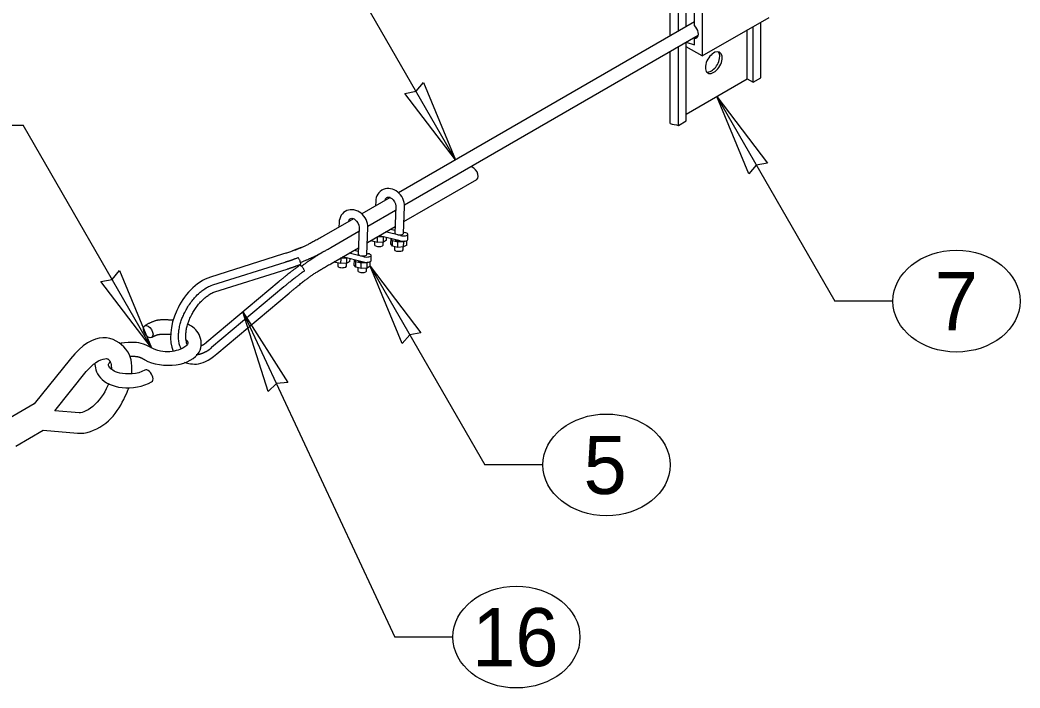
# Model space of a CAD drawing. Extents: x 99862 to 104211, y 98939 to 102076.
# Drawn here: x 101538.3 to 101813.6, y 101580.1 to 101763.9 of the extents above; entities that cross this region are included whole.
import ezdxf

# ---------------------------------------------------------------- set-up
doc = ezdxf.new("R2010")
doc.units = 0
for name, color, linetype in [('Default', 7, 'Continuous'), ('Level 15', 7, 'Continuous'), ('Level 2', 7, 'Continuous'), ('Level 20', 7, 'Continuous'), ('Level 3', 7, 'Continuous'), ('Level 4', 7, 'Continuous'), ('Level 6', 7, 'Continuous')]:
    doc.layers.add(name, color=color, linetype=linetype)

msp = doc.modelspace()

# ---------------------------------------------------------------- linework, layer by layer
at = {"layer": 'Default'}
for p, q in [((101717.25, 101759.56), (101717.25, 101858.02)), ((101719.53, 101760.88), (101719.53, 101857.5)), ((101721.65, 101762.1), (101721.65, 101857.19)), ((101726.09, 101782.05), (101726.09, 101754.01)), ((101723.96, 101762.39), (101723.96, 101781.42)), ((101726.09, 101754.01), (101744.49, 101764.64)), ((101742.18, 101747.99), (101742.18, 101763.3)), ((101738.47, 101747.69), (101738.47, 101761.16)), ((101740.06, 101746.77), (101740.06, 101762.08)), ((101721.65, 101736.14), (101721.65, 101757.77)), ((101721.68, 101757.79), (101723.96, 101757.09)), ((101723.96, 101758.93), (101724.93, 101759.49)), ((101723.96, 101757.09), (101723.96, 101758.93)), ((101717.25, 101735.44), (101717.25, 101755.23)), ((101719.53, 101734.92), (101719.53, 101756.55)), ((101726.09, 101754.01), (101721.65, 101756.57)), ((101721.65, 101737.98), (101738.47, 101747.69)), ((101738.47, 101747.69), (101740.06, 101746.77)), ((101740.06, 101746.77), (101742.18, 101747.99)), ((101719.53, 101734.92), (101721.65, 101736.14))]:
    msp.add_line(p, q, dxfattribs=at)
for centre, major_axis, start_param, end_param in [((101723.43, 101760.97), (1.13, -1.95), 0, 2.016358), ((101723.43, 101760.97), (1.13, -1.95), 5.837624, 6.283185), ((101729.26, 101752.18), (-1.64, -2.84), 2.543744, 6.283185), ((101728.6, 101752.56), (1.64, 2.84), 3.926991, 6.079755), ((101729.26, 101752.18), (-1.64, -2.84), 6.283185, 8.826929), ((101728.6, 101752.56), (1.64, 2.84), 3.345023, 3.926991), ((101725.02, 101744.82), (-18.02, 0), 1.125235, 1.261517)]:
    msp.add_ellipse(centre, major_axis=major_axis, ratio=0.57735, start_param=start_param, end_param=end_param, dxfattribs=at)
at = {"layer": 'Level 15'}
for p, q in [((101658.16, 101725.45), (101625.66, 101781.74)), ((101730.06, 101742.83), (101762.56, 101686.54)), ((101523.11, 101734.94), (101539.11, 101734.94)), ((101574.48, 101673.67), (101539.11, 101734.94)), ((101634.65, 101696.12), (101666.21, 101641.47)), ((101778.56, 101686.54), (101762.56, 101686.54)), ((101599.64, 101683.62), (101641.42, 101594.08)), ((101682.21, 101641.47), (101666.21, 101641.47)), ((101657.42, 101594.08), (101641.42, 101594.08))]:
    msp.add_line(p, q, dxfattribs=at)
for points in [[(101658.16, 101725.45), (101644.16, 101743.72), (101647.28, 101744.3), (101649.33, 101746.71)], [(101730.06, 101742.83), (101744.06, 101724.55), (101740.95, 101723.98), (101738.89, 101721.57)], [(101574.48, 101673.67), (101560.49, 101691.95), (101563.6, 101692.52), (101565.65, 101694.93)], [(101634.65, 101696.12), (101648.65, 101677.85), (101645.54, 101677.27), (101643.48, 101674.86)], [(101599.64, 101683.62), (101612, 101664.19), (101608.85, 101663.89), (101606.59, 101661.67)]]:
    msp.add_lwpolyline(points, close=True, dxfattribs=at)
at = {"layer": 'Level 2'}
for p, q in [((101636.19, 101714.01), (101636.15, 101712.74)), ((101641.69, 101712.68), (101641.46, 101705.25)), ((101643.86, 101705.18), (101644.1, 101712.61)), ((101626.11, 101708.19), (101626.07, 101706.92)), ((101631.61, 101706.86), (101631.38, 101699.43)), ((101633.78, 101699.36), (101634.02, 101706.79)), ((101642.95, 101703.12), (101637.11, 101704.52)), ((101643, 101704.59), (101638.92, 101705.57)), ((101640.29, 101706.35), (101641.48, 101706.07)), ((101643.87, 101705.49), (101644.21, 101705.41)), ((101644.99, 101703.47), (101645.04, 101704.94)), ((101635.22, 101703.03), (101635.02, 101703.32)), ((101635.22, 101703.03), (101635.24, 101703.44)), ((101636.67, 101702.68), (101635.22, 101703.03)), ((101635.84, 101702.88), (101635.82, 101702.04)), ((101636.72, 101704.13), (101636.51, 101704.18)), ((101636.67, 101702.68), (101636.72, 101704.13)), ((101638.31, 101702.78), (101636.67, 101702.68)), ((101638.32, 101704.23), (101636.72, 101704.13)), ((101638.22, 101701.96), (101638.25, 101702.78)), ((101638.31, 101702.78), (101638.35, 101704.22)), ((101639.17, 101703.28), (101638.31, 101702.78)), ((101639.17, 101703.28), (101639.19, 101704.02)), ((101640.37, 101702.29), (101640.42, 101703.73)), ((101640.79, 101701.69), (101640.37, 101702.29)), ((101640.83, 101703.14), (101640.43, 101703.72)), ((101640.79, 101701.69), (101640.83, 101703.14)), ((101642.28, 101702.79), (101640.83, 101703.14)), ((101642.24, 101701.34), (101642.28, 101702.79)), ((101643.92, 101702.89), (101642.28, 101702.79)), ((101643.87, 101701.45), (101643.92, 101702.89)), ((101644.73, 101701.94), (101643.87, 101701.45)), ((101644.2, 101703.06), (101643.92, 101702.89)), ((101644.73, 101701.94), (101644.77, 101703.22)), ((101632.92, 101698.77), (101628.84, 101699.75)), ((101630.21, 101700.53), (101631.4, 101700.25)), ((101633.79, 101699.67), (101634.13, 101699.59)), ((101634.91, 101697.65), (101634.95, 101699.12)), ((101642.24, 101701.34), (101640.79, 101701.69)), ((101641.34, 101701.56), (101641.32, 101700.72)), ((101643.87, 101701.45), (101642.24, 101701.34)), ((101643.72, 101700.64), (101643.75, 101701.44)), ((101625.14, 101697.21), (101624.94, 101697.5)), ((101625.14, 101697.21), (101625.16, 101697.62)), ((101626.59, 101696.86), (101625.14, 101697.21)), ((101625.76, 101697.06), (101625.74, 101696.22)), ((101626.64, 101698.31), (101626.43, 101698.36)), ((101626.59, 101696.86), (101626.64, 101698.31)), ((101628.23, 101696.96), (101626.59, 101696.86)), ((101628.24, 101698.41), (101626.64, 101698.31)), ((101632.87, 101697.3), (101627.03, 101698.7)), ((101628.14, 101696.14), (101628.17, 101696.96)), ((101628.23, 101696.96), (101628.27, 101698.4)), ((101629.09, 101697.46), (101628.23, 101696.96)), ((101629.09, 101697.46), (101629.11, 101698.2)), ((101630.29, 101696.47), (101630.34, 101697.91)), ((101630.71, 101695.87), (101630.29, 101696.47)), ((101630.75, 101697.32), (101630.35, 101697.9)), ((101630.71, 101695.87), (101630.75, 101697.32)), ((101632.2, 101696.97), (101630.75, 101697.32)), ((101632.16, 101695.52), (101632.2, 101696.97)), ((101633.84, 101697.07), (101632.2, 101696.97)), ((101633.79, 101695.63), (101633.84, 101697.07)), ((101634.12, 101697.24), (101633.84, 101697.07)), ((101634.65, 101696.12), (101634.69, 101697.4)), ((101632.16, 101695.52), (101630.71, 101695.87)), ((101631.26, 101695.74), (101631.24, 101694.9)), ((101633.79, 101695.63), (101632.16, 101695.52)), ((101633.64, 101694.82), (101633.67, 101695.62)), ((101634.65, 101696.12), (101633.79, 101695.63))]:
    msp.add_line(p, q, dxfattribs=at)
for centre, major_axis, start_param, end_param in [((101642.66, 101705.22), (1.2, -0.04), 3.141593, 6.283293), ((101643.69, 101704.98), (-1.34, 0.04), 1.037657, 4.329758), ((101637.02, 101702), (-1.2, 0.04), 6.283185, 9.424855), ((101642.61, 101703.56), (1.2, -0.04), 3.423218, 4.952465), ((101643.65, 101703.51), (-1.34, 0.04), 1.037657, 3.141593), ((101632.58, 101699.4), (1.2, -0.04), 3.141593, 6.283293), ((101633.61, 101699.16), (-1.34, 0.04), 1.037657, 4.329758), ((101642.52, 101700.68), (-1.2, 0.04), 6.283185, 9.424916), ((101632.53, 101697.74), (1.2, -0.04), 3.423218, 4.952465), ((101633.57, 101697.69), (-1.34, 0.04), 1.037657, 3.141593), ((101626.94, 101696.18), (-1.2, 0.04), 6.283185, 9.424855), ((101632.44, 101694.86), (-1.2, 0.04), 6.283185, 9.424916)]:
    msp.add_ellipse(centre, major_axis=major_axis, ratio=0.358054, start_param=start_param, end_param=end_param, dxfattribs=at)
for points in [[(101644.1, 101712.61), (101644.16, 101714.09), (101642.67, 101717.18), (101637.9, 101718.09), (101636.2, 101715.42), (101636.19, 101714.01)], [(101638.82, 101714.28), (101638.93, 101714.91), (101639.31, 101715.21), (101640.58, 101715.18), (101641.7, 101713.52), (101641.69, 101712.68)], [(101634.02, 101706.79), (101634.08, 101708.27), (101632.59, 101711.36), (101627.82, 101712.27), (101626.12, 101709.6), (101626.11, 101708.19)], [(101628.74, 101708.46), (101628.85, 101709.09), (101629.22, 101709.39), (101630.5, 101709.36), (101631.62, 101707.7), (101631.61, 101706.86)]]:
    msp.add_open_spline(points, degree=3, dxfattribs=at)
at = {"layer": 'Level 20'}
for centre in [(101796.06, 101686.54), (101699.71, 101641.47), (101674.92, 101594.08)]:
    msp.add_ellipse(centre, major_axis=(-17.5, 0), ratio=0.8, dxfattribs=at)
at = {"layer": 'Level 3'}
for p, q in [((101623.81, 101701.28), (101631.58, 101705.77)), ((101613.41, 101700.46), (101615.74, 101701.43)), ((101623.81, 101696.84), (101631.44, 101701.24)), ((101591.34, 101691.01), (101611.24, 101697.29)), ((101591.94, 101689.11), (101611.84, 101695.38)), ((101609.6, 101691.98), (101589.68, 101675.26)), ((101610.89, 101690.45), (101590.98, 101673.74)), ((101552.13, 101670.66), (101542.15, 101658.25)), ((101547.87, 101656.39), (101556.51, 101667.14)), ((101542.15, 101658.25), (101533.33, 101653.16)), ((101554.57, 101655.79), (101547.87, 101656.39)), ((101537.08, 101646.66), (101544.65, 101651.03)), ((101544.65, 101651.03), (101554.07, 101650.19))]:
    msp.add_line(p, q, dxfattribs=at)
for centre, major_axis, ratio, start_param, end_param in [((101663.03, 101721.73), (-0.95, 1.69), 0.573607, 3.151047, 6.083428), ((101554.32, 101668.9), (-2.19, 1.76), 0.21132, 6.282192, 6.283184)]:
    msp.add_ellipse(centre, major_axis=major_axis, ratio=ratio, start_param=start_param, end_param=end_param, dxfattribs=at)
for points, degree in [([(101615.48, 101697.21), (101618.24, 101698.31), (101621.03, 101699.68), (101623.81, 101701.28)], 2), ([(101621.88, 101700.21), (101619.84, 101698.95), (101617.79, 101697.6), (101615.75, 101696.13)], 2), ([(101615.36, 101696.47), (101613.09, 101694.81), (101611.33, 101693.44), (101609.6, 101691.98)], 2), ([(101611.24, 101697.29), (101612.25, 101697.61), (101613.27, 101697.96), (101614.83, 101698.52)], 2), ([(101611.84, 101695.38), (101612.91, 101695.72), (101613.99, 101696.1), (101615.58, 101696.71)], 2), ([(101615.58, 101696.71), (101615.57, 101696.74), (101615.57, 101696.78), (101615.52, 101697.08), (101615.45, 101697.34), (101615.26, 101697.84), (101615.14, 101698.07), (101614.94, 101698.37), (101614.89, 101698.45), (101614.83, 101698.52)], 3), ([(101616.58, 101694.88), (101616.57, 101694.91), (101616.56, 101694.94), (101616.44, 101695.23), (101616.31, 101695.46), (101615.99, 101695.89), (101615.82, 101696.08), (101615.54, 101696.33), (101615.45, 101696.4), (101615.36, 101696.47)], 3), ([(101616.58, 101694.88), (101614.36, 101693.26), (101612.61, 101691.9), (101610.89, 101690.45)], 2), ([(101582.65, 101673.39), (101582.28, 101674.12), (101582.11, 101674.72), (101581.89, 101676.14), (101581.86, 101676.96), (101581.97, 101678.29), (101582.04, 101678.75), (101582.22, 101679.68), (101582.34, 101680.15), (101582.76, 101681.55), (101583.14, 101682.48), (101584.04, 101684.29), (101584.57, 101685.17), (101585.74, 101686.81), (101586.39, 101687.58), (101587.75, 101688.92), (101588.46, 101689.5), (101589.9, 101690.44), (101590.62, 101690.8), (101591.36, 101691.02)], 3), ([(101584.28, 101674.59), (101584.16, 101674.88), (101584.05, 101675.24), (101583.9, 101676.26), (101583.87, 101676.94), (101583.99, 101678.42), (101584.15, 101679.22), (101584.64, 101680.85), (101584.98, 101681.68), (101585.79, 101683.31), (101586.26, 101684.1), (101587.31, 101685.57), (101587.88, 101686.24), (101589.07, 101687.41), (101589.68, 101687.91), (101590.87, 101688.68), (101591.44, 101688.96), (101591.93, 101689.1)], 3), ([(101569.01, 101666.65), (101569.25, 101669.52), (101568.36, 101673.56), (101561.45, 101678.04), (101555.39, 101674.69), (101552.13, 101670.66)], 3), ([(101589.68, 101675.26), (101589.21, 101674.81), (101588.66, 101674.46), (101588.14, 101674.19)], 2), ([(101588.56, 101672.18), (101588.05, 101671.98), (101587.55, 101671.85), (101586.74, 101671.72)], 2), ([(101591.06, 101673.81), (101590.25, 101673.04), (101589.36, 101672.53), (101588.56, 101672.18)], 2), ([(101556.51, 101667.14), (101557.36, 101668.11), (101559.13, 101670), (101561.99, 101670.85), (101562.6, 101670.64), (101563.31, 101669.65), (101563.43, 101668.28), (101563.43, 101667.86)], 3), ([(101562.67, 101663.87), (101561.95, 101661.94), (101559.15, 101657.38), (101555.36, 101655.68), (101554.57, 101655.79)], 3), ([(101554.07, 101650.19), (101556.32, 101650.02), (101561.6, 101651.79), (101566.41, 101657.92), (101567.98, 101662.06), (101568.21, 101662.76)], 3)]:
    msp.add_open_spline(points, degree=degree, dxfattribs=at)
at = {"layer": 'Level 4'}
msp.add_ellipse((101573.55, 101678.17), major_axis=(-0.94, 1.62), ratio=0.57735, dxfattribs=at)
msp.add_ellipse((101573.55, 101665.92), major_axis=(-0.94, 1.62), ratio=0.57735, start_param=3.141593, end_param=6.304048, dxfattribs=at)
for points, degree in [([(101580.36, 101681.26), (101577.62, 101681.52), (101574.68, 101681), (101572.61, 101679.79)], 2), ([(101572.61, 101670.42), (101574.75, 101669.14), (101581.9, 101668.07), (101588.87, 101672.21), (101587.88, 101677.86), (101585.86, 101679.55), (101584.45, 101680.21)], 3), ([(101574.48, 101676.54), (101575.7, 101677.28), (101577.76, 101677.55), (101579.67, 101677.43)], 2), ([(101574.48, 101673.67), (101572.34, 101674.95), (101569.1, 101675.43), (101566.13, 101674.99), (101566, 101674.97)], 3), ([(101583.94, 101675.99), (101584.15, 101675.79), (101584.48, 101675.36), (101584.56, 101675.04), (101584.01, 101673.88), (101579.78, 101672.2), (101575.89, 101672.81), (101574.48, 101673.67)], 3), ([(101558.9, 101669.49), (101558.81, 101668.57), (101559.5, 101665.12), (101565.78, 101662), (101572.27, 101663), (101574.48, 101664.3)], 3), ([(101572.61, 101667.54), (101570.58, 101666.31), (101564.57, 101666.39), (101562.63, 101668.65), (101562.55, 101668.99), (101562.77, 101669.51), (101563.09, 101669.84)], 3), ([(101568.51, 101671.44), (101570.1, 101671.4), (101571.64, 101671.02), (101572.61, 101670.42)], 2)]:
    msp.add_open_spline(points, degree=degree, dxfattribs=at)
at = {"layer": 'Level 6'}
for p, q in [((101723.96, 101763.44), (101642.46, 101716.38)), ((101644.1, 101713), (101724.99, 101759.7)), ((101643.97, 101708.48), (101663.99, 101720.04)), ((101640.15, 101715.05), (101632.37, 101710.56)), ((101634.02, 101707.18), (101641.66, 101711.59)), ((101630.07, 101709.23), (101621.93, 101704.53)), ((101633.89, 101702.66), (101641.52, 101707.06)), ((101610.56, 101699.43), (101590.66, 101693.16)), ((101592.43, 101672.02), (101612.33, 101688.73))]:
    msp.add_line(p, q, dxfattribs=at)
for points, degree in [([(101621.93, 101704.53), (101618.09, 101702.31), (101614.27, 101700.6), (101610.56, 101699.43)], 2), ([(101612.33, 101688.73), (101616.1, 101691.89), (101619.96, 101694.62), (101623.81, 101696.84)], 2), ([(101590.66, 101693.16), (101586.73, 101691.92), (101579.82, 101684.25), (101579.2, 101675.43), (101580.44, 101672.76)], 3), ([(101583.49, 101669.75), (101583.9, 101669.57), (101586.74, 101668.68), (101590.04, 101670.01), (101592.43, 101672.02)], 3)]:
    msp.add_open_spline(points, degree=degree, dxfattribs=at)

# ---------------------------------------------------------------- texts
at = {"layer": 'Level 20'}
for s, p in [('7', (101790.11, 101678.54)), ('5', (101693.4, 101633.47)), ('16', (101662.72, 101586.08))]:
    msp.add_text(s, height=16, dxfattribs=at).set_placement(p)

doc.saveas('drawing.dxf')
